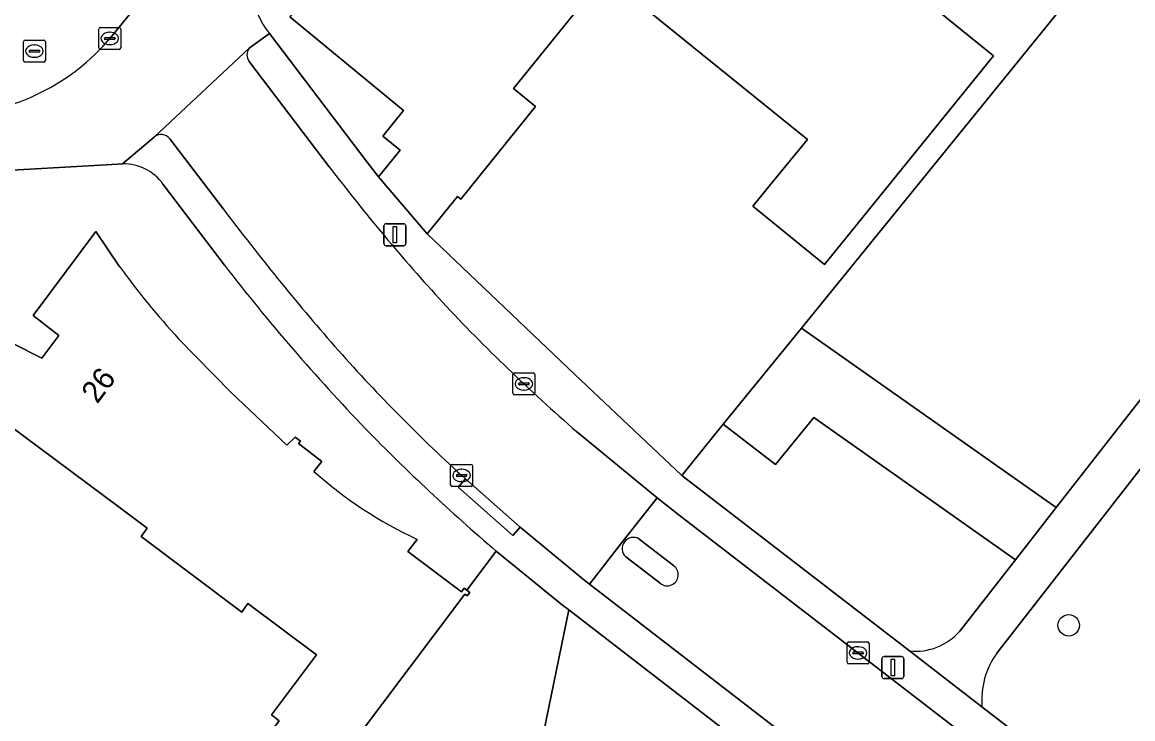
# Model space of a CAD drawing. Extents: x 159499 to 160349, y 382524 to 383273.
# Drawn here: x 159995.6 to 160046.1, y 382929.5 to 382961.2 of the extents above; entities that cross this region are included whole.
import ezdxf

# ---------------------------------------------------------------- set-up
doc = ezdxf.new("R2010")
doc.units = 0
for name, color, linetype in [('IMGEO_Boom', 7, 'Continuous'), ('IMGEO_Erf', 7, 'Continuous'), ('IMGEO_Fietspad_open', 7, 'Continuous'), ('IMGEO_Groenvoorziening', 7, 'Continuous'), ('IMGEO_Kolk', 7, 'Continuous'), ('IMGEO_Lichtmast', 7, 'Continuous'), ('IMGEO_Muur', 7, 'Continuous'), ('IMGEO_Pand', 7, 'Continuous'), ('IMGEO_Pand_nummerreeks', 7, 'Continuous'), ('IMGEO_Rijbaan_lokaal_open', 7, 'Continuous'), ('IMGEO_Rioolput', 7, 'Continuous'), ('IMGEO_Verkeerseiland_open', 7, 'Continuous'), ('IMGEO_Voetpad_halfverhard', 7, 'Continuous'), ('IMGEO_Voetpad_open', 7, 'Continuous')]:
    doc.layers.add(name, color=color, linetype=linetype)

msp = doc.modelspace()

# ---------------------------------------------------------------- linework, layer by layer
at = {"layer": 'IMGEO_Boom'}
msp.add_circle((160043.163, 382933.794), 0.489, dxfattribs=at)
at = {"layer": 'IMGEO_Erf'}
for points in [[(160035.463, 382963.138), (160039.738, 382959.678), (160032.064, 382950.194), (160028.799, 382952.836), (160029.96, 382954.246), (160031.282, 382955.879), (160022.074, 382963.331), (160017.918, 382958.195), (160018.929, 382957.378), (160015.521, 382953.167), (160015.375, 382953.286), (160014.004, 382951.592), (160020.709, 382945.19), (160025.568, 382940.607), (160027.46, 382942.936), (160031.009, 382947.305), (160052.413, 382973.653)], [(160006.829, 382960.689), (160011.264, 382954.849), (160011.78, 382954.169), (160012.771, 382955.393), (160011.986, 382956.029), (160012.916, 382957.191), (160007.749, 382961.454)], [(160000.149, 382954.763), (159999.933, 382954.745), (159991.369, 382954.262), (159973.432, 382953.353)], [(160004.784, 382950.166), (160002.003, 382953.831)], [(159975.215, 382950.328), (159980.908, 382950.668), (159981.031, 382949.203), (159983.01, 382949.322), (159986.119, 382949.51), (159986.572, 382941.868), (159989.763, 382942.076), (159989.318, 382949.49), (159995.132, 382946.61), (159996.488, 382945.938), (159997.261, 382946.967), (159996.091, 382947.877), (159998.929, 382951.684), (160000, 382950.12)], [(160002.7, 382946.812), (160005.083, 382944.371), (160007.614, 382941.975), (160007.996, 382942.341), (160008.233, 382942.163), (160008.156, 382942.059), (160009.209, 382941.236), (160008.85, 382940.79)], [(159952.688, 382921.969), (160000, 382924.568), (160007.956, 382925.066), (160009.503, 382926.949), (160006.867, 382928.928), (160007.264, 382929.458), (160006.918, 382929.718), (160008.967, 382932.449), (160005.846, 382934.79), (160005.569, 382934.389), (160000.995, 382937.827), (160001.276, 382938.205), (160000, 382939.157), (159994.951, 382942.922)], [(160013.538, 382937.7), (160013.118, 382937.14), (160015.556, 382935.309), (160015.682, 382935.477), (160015.807, 382935.383), (160017.142, 382937.168)]]:
    msp.add_lwpolyline(points, dxfattribs=at)
for centre, radius, start, end in [((160009.628, 382962.985), 3.62, 154.4733, 219.3669), ((160000.212, 382952.579), 2.185, 34.9601, 91.6628), ((160029.875, 382971.748), 36.882, 215.9029, 222.54), ((160074.156, 383003.511), 87.511, 217.55944, 223.99367), ((160074.022, 383003.922), 87.701, 224.24761, 229.56638), ((160021.675, 382955.147), 19.251, 228.2247, 244.9952)]:
    msp.add_arc(centre, radius, start, end, dxfattribs=at)
at = {"layer": 'IMGEO_Fietspad_open'}
for points in [[(160005.908, 382960.021), (160001.602, 382955.996)], [(160009.545, 382954.631), (160005.905, 382959.423)], [(160002.3, 382955.907), (160004.746, 382952.7)], [(160015.569, 382940.601), (160015.738, 382940.446), (160018.22, 382938.246), (160021.106, 382935.882), (160021.378, 382935.67), (160022.909, 382937.636), (160024.456, 382939.589), (160020.788, 382942.6)], [(160025.459, 382938.803), (160024.456, 382939.589), (160022.909, 382937.636), (160021.378, 382935.67), (160063.074, 382903.483), (160066.117, 382901.155), (160068.062, 382899.707), (160072.665, 382896.136)], [(160076.227, 382899.664), (160069.998, 382904.476), (160025.459, 382938.803)], [(160023.624, 382937.724), (160025.194, 382936.508)], [(160024.589, 382935.703), (160023.026, 382936.902)]]:
    msp.add_lwpolyline(points, dxfattribs=at)
for centre, radius, start, end in [((160006.291, 382959.72), 0.487, 141.8673, 217.5579), ((160001.906, 382955.602), 0.498, 37.7654, 127.7017), ((160081.386, 383009.489), 90.391, 217.36539, 222.45416), ((160092.923, 383019.042), 110.347, 216.95678, 221.11214), ((160075.343, 383005.287), 83.102, 223.12889, 228.96758), ((160068.005, 382997.931), 77.694, 221.46522, 227.5527), ((160023.377, 382937.276), 0.512, 61.093, 142.5695), ((160023.361, 382937.274), 0.501, 141.3505, 227.9967), ((160024.908, 382936.093), 0.504, 230.689, 55.4574)]:
    msp.add_arc(centre, radius, start, end, dxfattribs=at)
at = {"layer": 'IMGEO_Groenvoorziening'}
for points in [[(160064.767, 383037.736), (160064.154, 383036.884), (160086.515, 383015.238), (160074.019, 383000), (160052.413, 382973.653), (160031.009, 382947.305), (160042.591, 382939.142), (160050.543, 382949.325), (160056.483, 382957.417)], [(160039.216, 382930.091), (160066.447, 382909.109), (160081.958, 382927.957), (160078.777, 382930.867), (160081.343, 382933.929), (160066.591, 382946.291), (160078.07, 382965.324), (160067.823, 382973.903)], [(160064.191, 382966.975), (160061.224, 382961.584), (160058.065, 382956.302), (160055.15, 382952.189), (160052.089, 382948.183), (160039.892, 382932.533)], [(160038.205, 382933.526), (160040.742, 382936.775), (160031.571, 382943.239), (160029.837, 382941.105), (160027.46, 382942.936), (160025.568, 382940.607), (160035.923, 382932.628)], [(160017.276, 382919.096), (160020.444, 382934.49), (160020.156, 382934.712), (160017.142, 382937.168), (160015.807, 382935.383), (160015.93, 382935.29), (160015.81, 382935.13), (160015.706, 382935.209), (160009.503, 382926.949), (160007.956, 382925.066), (160000, 382924.568), (159952.688, 382921.969), (159935.493, 382907.023), (159936.535, 382905.918), (159939.597, 382902.666), (159962.238, 382916.541), (159978.374, 382915.464)], [(160030.14, 382927.014), (160020.444, 382934.49), (160017.276, 382919.096)]]:
    msp.add_lwpolyline(points, dxfattribs=at)
msp.add_lwpolyline([(160031.009, 382947.305), (160027.46, 382942.936), (160029.837, 382941.105), (160031.571, 382943.239), (160040.742, 382936.775), (160042.591, 382939.142)], close=True, dxfattribs=at)
for centre, radius, start, end in [((160036.194, 382935.288), 2.674, 264.1891, 318.7716), ((160042.931, 382930.377), 3.726, 144.6503, 184.4032)]:
    msp.add_arc(centre, radius, start, end, dxfattribs=at)
at = {"layer": 'IMGEO_Kolk'}
for p, q in [((159999.141, 382960.965), (159999.993, 382960.965)), ((159999.066, 382960.039), (159999.066, 382960.891)), ((159999.325, 382960.459), (159999.325, 382960.471)), ((159999.763, 382960.422), (159999.365, 382960.422)), ((159999.368, 382960.508), (159999.766, 382960.508)), ((159999.554, 382960.745), (159999.579, 382960.745)), ((159999.809, 382960.471), (159999.809, 382960.459)), ((160000.067, 382960.891), (160000.067, 382960.039)), ((159999.993, 382959.965), (159999.141, 382959.965)), ((159999.577, 382960.185), (159999.552, 382960.185)), ((160017.896, 382944.34), (160017.896, 382945.192)), ((160017.971, 382945.266), (160018.823, 382945.266)), ((160018.155, 382944.76), (160018.155, 382944.772)), ((160018.198, 382944.809), (160018.596, 382944.809)), ((160018.384, 382945.046), (160018.409, 382945.046)), ((160018.639, 382944.772), (160018.639, 382944.76)), ((160018.897, 382945.192), (160018.897, 382944.34)), ((160018.823, 382944.266), (160017.971, 382944.266)), ((160018.593, 382944.723), (160018.195, 382944.723)), ((160018.407, 382944.486), (160018.382, 382944.486)), ((160015.065, 382940.177), (160015.065, 382941.029)), ((160015.14, 382941.103), (160015.992, 382941.103)), ((160015.553, 382940.883), (160015.578, 382940.883)), ((160016.066, 382941.029), (160016.066, 382940.177)), ((160015.324, 382940.597), (160015.324, 382940.609)), ((160015.762, 382940.56), (160015.364, 382940.56)), ((160015.367, 382940.646), (160015.765, 382940.646)), ((160015.576, 382940.323), (160015.551, 382940.323)), ((160015.808, 382940.609), (160015.808, 382940.597)), ((160015.992, 382940.103), (160015.14, 382940.103)), ((160033.086, 382932.111), (160033.086, 382932.963)), ((160033.161, 382933.037), (160034.013, 382933.037)), ((160033.574, 382932.817), (160033.599, 382932.817)), ((160034.087, 382932.963), (160034.087, 382932.111)), ((160033.345, 382932.531), (160033.345, 382932.543)), ((160033.783, 382932.494), (160033.385, 382932.494)), ((160033.388, 382932.58), (160033.786, 382932.58)), ((160033.597, 382932.257), (160033.572, 382932.257)), ((160033.829, 382932.543), (160033.829, 382932.531)), ((160034.013, 382932.037), (160033.161, 382932.037))]:
    msp.add_line(p, q, dxfattribs=at)
for points in [[(159999.141, 382960.965), (159999.993, 382960.965)], [(159999.066, 382960.039), (159999.066, 382960.891)], [(160000.067, 382960.891), (160000.067, 382960.039)], [(159999.993, 382959.965), (159999.141, 382959.965)], [(160017.896, 382944.34), (160017.896, 382945.192)], [(160017.971, 382945.266), (160018.823, 382945.266)], [(160018.897, 382945.192), (160018.897, 382944.34)], [(160018.823, 382944.266), (160017.971, 382944.266)], [(160015.065, 382940.177), (160015.065, 382941.029)], [(160015.14, 382941.103), (160015.992, 382941.103)], [(160016.066, 382941.029), (160016.066, 382940.177)], [(160015.992, 382940.103), (160015.14, 382940.103)], [(160033.086, 382932.111), (160033.086, 382932.963)], [(160033.161, 382933.037), (160034.013, 382933.037)], [(160034.087, 382932.963), (160034.087, 382932.111)], [(160034.013, 382932.037), (160033.161, 382932.037)]]:
    msp.add_lwpolyline(points, dxfattribs=at)
for centre, radius, start, end in [((159999.143, 382960.889), 0.0765, 91.552, 178.448), ((159999.143, 382960.889), 0.0765, 91.552, 178.448), ((159999.991, 382960.889), 0.0765, 1.552, 88.448), ((159999.991, 382960.889), 0.0765, 1.552, 88.448), ((159999.365, 382960.468), 0.0403, 85.8775, 175.7526), ((159999.362, 382960.458), 0.0366, 178.938, 274.7102), ((159999.766, 382960.465), 0.043, 264.8664, 352.4533), ((159999.77, 382960.47), 0.0386, 1.7309, 96.639), ((159999.143, 382960.041), 0.0765, 181.552, 268.448), ((159999.143, 382960.041), 0.0765, 181.552, 268.448), ((159999.991, 382960.041), 0.0765, 271.552, 358.448), ((159999.991, 382960.041), 0.0765, 271.552, 358.448), ((160017.973, 382945.19), 0.0765, 91.552, 178.448), ((160017.973, 382945.19), 0.0765, 91.552, 178.448), ((160018.195, 382944.769), 0.0403, 85.8775, 175.7526), ((160018.6, 382944.771), 0.0386, 1.7309, 96.639), ((160018.821, 382945.19), 0.0765, 1.552, 88.448), ((160018.821, 382945.19), 0.0765, 1.552, 88.448), ((160017.973, 382944.342), 0.0765, 181.552, 268.448), ((160017.973, 382944.342), 0.0765, 181.552, 268.448), ((160018.192, 382944.759), 0.0366, 178.938, 274.7102), ((160018.596, 382944.766), 0.043, 264.8664, 352.4533), ((160018.821, 382944.342), 0.0765, 271.552, 358.448), ((160018.821, 382944.342), 0.0765, 271.552, 358.448), ((160015.142, 382941.027), 0.0765, 91.552, 178.448), ((160015.142, 382941.027), 0.0765, 91.552, 178.448), ((160015.99, 382941.027), 0.0765, 1.552, 88.448), ((160015.99, 382941.027), 0.0765, 1.552, 88.448), ((160015.364, 382940.606), 0.0403, 85.8775, 175.7526), ((160015.361, 382940.596), 0.0366, 178.938, 274.7102), ((160015.765, 382940.603), 0.043, 264.8664, 352.4533), ((160015.769, 382940.608), 0.0386, 1.7309, 96.639), ((160015.142, 382940.179), 0.0765, 181.552, 268.448), ((160015.142, 382940.179), 0.0765, 181.552, 268.448), ((160015.99, 382940.179), 0.0765, 271.552, 358.448), ((160015.99, 382940.179), 0.0765, 271.552, 358.448), ((160033.163, 382932.961), 0.0765, 91.552, 178.448), ((160033.163, 382932.961), 0.0765, 91.552, 178.448), ((160034.011, 382932.961), 0.0765, 1.552, 88.448), ((160034.011, 382932.961), 0.0765, 1.552, 88.448), ((160033.385, 382932.54), 0.0403, 85.8775, 175.7526), ((160033.382, 382932.53), 0.0366, 178.938, 274.7102), ((160033.786, 382932.537), 0.043, 264.8664, 352.4533), ((160033.79, 382932.542), 0.0386, 1.7309, 96.639), ((160033.163, 382932.113), 0.0765, 181.552, 268.448), ((160033.163, 382932.113), 0.0765, 181.552, 268.448), ((160034.011, 382932.113), 0.0765, 271.552, 358.448), ((160034.011, 382932.113), 0.0765, 271.552, 358.448)]:
    msp.add_arc(centre, radius, start, end, dxfattribs=at)
for centre, major_axis, ratio, start_param, end_param in [((159999.553, 382960.465), (-0.387, 0.002), 0.722429, 4.712389, 7.853982), ((159999.578, 382960.465), (-0.39, 0.002), 0.717154, 1.570796, 4.712389), ((160018.383, 382944.766), (-0.387, 0.002), 0.722429, 4.712389, 7.853982), ((160018.408, 382944.766), (-0.39, 0.002), 0.717154, 1.570796, 4.712389), ((160015.552, 382940.603), (-0.387, 0.002), 0.722429, 4.712389, 7.853982), ((160015.577, 382940.603), (-0.39, 0.002), 0.717154, 1.570796, 4.712389), ((160033.573, 382932.537), (-0.387, 0.002), 0.722429, 4.712389, 7.853982), ((160033.598, 382932.537), (-0.39, 0.002), 0.717154, 1.570796, 4.712389)]:
    msp.add_ellipse(centre, major_axis=major_axis, ratio=ratio, start_param=start_param, end_param=end_param, dxfattribs=at)
at = {"layer": 'IMGEO_Lichtmast'}
for p, q in [((160012.033, 382951.144), (160012.033, 382951.944)), ((160012.033, 382951.944), (160012.033, 382951.144)), ((160012.133, 382952.044), (160012.923, 382952.044)), ((160012.923, 382952.044), (160012.133, 382952.044)), ((160013.023, 382951.944), (160013.023, 382951.144)), ((160013.023, 382951.144), (160013.023, 382951.944)), ((160012.923, 382951.044), (160012.133, 382951.044)), ((160012.133, 382951.044), (160012.923, 382951.044)), ((160034.672, 382931.473), (160034.672, 382932.273)), ((160034.672, 382932.273), (160034.672, 382931.473)), ((160034.772, 382932.373), (160035.562, 382932.373)), ((160035.562, 382932.373), (160034.772, 382932.373)), ((160035.662, 382932.273), (160035.662, 382931.473)), ((160035.662, 382931.473), (160035.662, 382932.273)), ((160035.562, 382931.373), (160034.772, 382931.373)), ((160034.772, 382931.373), (160035.562, 382931.373))]:
    msp.add_line(p, q, dxfattribs=at)
for points in [[(160012.453, 382951.919), (160012.603, 382951.919), (160012.603, 382951.169), (160012.453, 382951.169), (160012.453, 382951.919)], [(160035.092, 382932.248), (160035.242, 382932.248), (160035.242, 382931.498), (160035.092, 382931.498), (160035.092, 382932.248)]]:
    msp.add_lwpolyline(points, dxfattribs=at)
for centre, start, end in [((160012.133, 382951.944), 90, 180), ((160012.133, 382951.944), 90, 180), ((160012.923, 382951.944), 0, 90), ((160012.923, 382951.944), 360, 90), ((160012.133, 382951.144), 180, 270), ((160012.133, 382951.144), 180, 270), ((160012.923, 382951.144), 270, 0), ((160012.923, 382951.144), 270, 0), ((160034.772, 382932.273), 90, 180), ((160034.772, 382932.273), 90, 180), ((160035.562, 382932.273), 0, 90), ((160035.562, 382932.273), 360, 90), ((160034.772, 382931.473), 180, 270), ((160034.772, 382931.473), 180, 270), ((160035.562, 382931.473), 270, 0), ((160035.562, 382931.473), 270, 0)]:
    msp.add_arc(centre, 0.1, start, end, dxfattribs=at)
at = {"layer": 'IMGEO_Muur'}
msp.add_lwpolyline([(160014.004, 382951.592), (160020.709, 382945.19)], dxfattribs=at)
at = {"layer": 'IMGEO_Pand'}
msp.add_lwpolyline([(160014.004, 382951.592), (160015.375, 382953.286), (160015.521, 382953.167), (160018.929, 382957.378), (160017.918, 382958.195), (160022.074, 382963.331), (160031.282, 382955.879), (160029.96, 382954.246), (160028.799, 382952.836), (160032.064, 382950.194), (160039.738, 382959.678), (160035.463, 382963.138), (160034.771, 382962.282), (160024.597, 382970.514), (160020.71, 382973.659), (160017.292, 382969.479), (160016.393, 382970.234), (160013.346, 382966.541), (160012.437, 382967.265), (160007.749, 382961.454), (160012.916, 382957.191), (160011.986, 382956.029), (160012.771, 382955.393), (160011.78, 382954.169)], close=True, dxfattribs=at)
for points in [[(160000, 382950.12), (159998.929, 382951.684), (159996.091, 382947.877), (159997.261, 382946.967), (159996.488, 382945.938), (159995.132, 382946.61)], [(160008.85, 382940.79), (160009.209, 382941.236), (160008.156, 382942.059), (160008.233, 382942.163), (160007.996, 382942.341), (160007.614, 382941.975), (160005.083, 382944.371), (160002.7, 382946.812)], [(159994.951, 382942.922), (160000, 382939.157), (160001.276, 382938.205), (160000.995, 382937.827), (160005.569, 382934.389), (160005.846, 382934.79), (160008.967, 382932.449), (160006.918, 382929.718), (160007.264, 382929.458), (160006.867, 382928.928), (160009.503, 382926.949), (160015.706, 382935.209), (160015.81, 382935.13), (160015.93, 382935.29), (160015.807, 382935.383), (160015.682, 382935.477), (160015.556, 382935.309), (160013.118, 382937.14), (160013.538, 382937.7)]]:
    msp.add_lwpolyline(points, dxfattribs=at)
for centre, radius, start, end in [((160029.875, 382971.748), 36.882, 215.9029, 222.54), ((160021.675, 382955.147), 19.251, 228.2247, 244.9952)]:
    msp.add_arc(centre, radius, start, end, dxfattribs=at)
at = {"layer": 'IMGEO_Rijbaan_lokaal_open'}
for points in [[(159999.59, 382960.475), (160000, 382960.98), (160004.421, 382966.424), (160007.59, 382970.326), (160016.821, 382981.656), (160020, 382985.559), (160027.604, 382994.891), (160030.786, 382998.795)], [(160006.361, 382964.545), (160005.808, 382965.295), (160004.421, 382966.424), (160000, 382960.98), (159999.59, 382960.475)], [(159973.432, 382953.353), (159991.369, 382954.262), (159999.933, 382954.745), (160000.149, 382954.763), (160001.602, 382955.996), (160005.908, 382960.021), (160006.829, 382960.689)]]:
    msp.add_lwpolyline(points, dxfattribs=at)
for centre, radius, start, end in [((160009.628, 382962.985), 3.62, 154.4733, 219.3669), ((159991.946, 382966.989), 10.043, 273.4358, 319.5641), ((159991.946, 382966.989), 10.043, 273.4358, 319.5641)]:
    msp.add_arc(centre, radius, start, end, dxfattribs=at)
at = {"layer": 'IMGEO_Rioolput'}
for p, q in [((159995.643, 382959.463), (159995.643, 382960.315)), ((159995.718, 382960.389), (159996.57, 382960.389)), ((159995.945, 382959.932), (159996.343, 382959.932)), ((159996.131, 382960.169), (159996.156, 382960.169)), ((159996.644, 382960.315), (159996.644, 382959.463)), ((159995.902, 382959.883), (159995.902, 382959.895)), ((159996.34, 382959.846), (159995.942, 382959.846)), ((159996.154, 382959.609), (159996.129, 382959.609)), ((159996.386, 382959.895), (159996.386, 382959.883)), ((159996.57, 382959.389), (159995.718, 382959.389))]:
    msp.add_line(p, q, dxfattribs=at)
for points in [[(159995.643, 382959.463), (159995.643, 382960.315)], [(159995.718, 382960.389), (159996.57, 382960.389)], [(159996.644, 382960.315), (159996.644, 382959.463)], [(159996.57, 382959.389), (159995.718, 382959.389)]]:
    msp.add_lwpolyline(points, dxfattribs=at)
for centre, radius, start, end in [((159995.72, 382960.313), 0.0765, 91.552, 178.448), ((159995.72, 382960.313), 0.0765, 91.552, 178.448), ((159995.942, 382959.892), 0.0403, 85.8775, 175.7526), ((159996.347, 382959.894), 0.0386, 1.7309, 96.639), ((159996.568, 382960.313), 0.0765, 1.552, 88.448), ((159996.568, 382960.313), 0.0765, 1.552, 88.448), ((159995.72, 382959.465), 0.0765, 181.552, 268.448), ((159995.72, 382959.465), 0.0765, 181.552, 268.448), ((159995.939, 382959.882), 0.0366, 178.938, 274.7102), ((159996.343, 382959.889), 0.043, 264.8664, 352.4533), ((159996.568, 382959.465), 0.0765, 271.552, 358.448), ((159996.568, 382959.465), 0.0765, 271.552, 358.448)]:
    msp.add_arc(centre, radius, start, end, dxfattribs=at)
for centre, major_axis, ratio, start_param, end_param in [((159996.13, 382959.889), (-0.387, 0.002), 0.722429, 4.712389, 7.853982), ((159996.155, 382959.889), (-0.39, 0.002), 0.717154, 1.570796, 4.712389)]:
    msp.add_ellipse(centre, major_axis=major_axis, ratio=ratio, start_param=start_param, end_param=end_param, dxfattribs=at)
at = {"layer": 'IMGEO_Verkeerseiland_open'}
for points in [[(160025.194, 382936.508), (160023.624, 382937.724)], [(160023.026, 382936.902), (160024.589, 382935.703)]]:
    msp.add_lwpolyline(points, dxfattribs=at)
for centre, radius, start, end in [((160023.377, 382937.276), 0.512, 61.093, 142.5695), ((160023.361, 382937.274), 0.501, 141.3505, 227.9967), ((160024.908, 382936.093), 0.504, 230.689, 55.4574)]:
    msp.add_arc(centre, radius, start, end, dxfattribs=at)
at = {"layer": 'IMGEO_Voetpad_halfverhard'}
for points in [[(160039.892, 382932.533), (160052.089, 382948.183), (160055.15, 382952.189), (160058.065, 382956.302), (160061.224, 382961.584), (160064.191, 382966.975)], [(160056.483, 382957.417), (160050.543, 382949.325), (160042.591, 382939.142), (160040.742, 382936.775), (160038.205, 382933.526)], [(160035.923, 382932.628), (160039.216, 382930.091)]]:
    msp.add_lwpolyline(points, dxfattribs=at)
for centre, radius, start, end in [((160036.194, 382935.288), 2.674, 264.1891, 318.7716), ((160042.931, 382930.377), 3.726, 144.6503, 184.4032)]:
    msp.add_arc(centre, radius, start, end, dxfattribs=at)
at = {"layer": 'IMGEO_Voetpad_open'}
for points in [[(160039.216, 382930.091), (160035.923, 382932.628), (160025.568, 382940.607), (160020.709, 382945.19), (160014.004, 382951.592), (160011.78, 382954.169), (160011.264, 382954.849), (160006.829, 382960.689), (160005.908, 382960.021)], [(160005.905, 382959.423), (160009.545, 382954.631)], [(160001.602, 382955.996), (160000.149, 382954.763)], [(160004.746, 382952.7), (160002.3, 382955.907)], [(160002.003, 382953.831), (160004.784, 382950.166)], [(160020.788, 382942.6), (160024.456, 382939.589), (160025.459, 382938.803), (160069.998, 382904.476), (160076.227, 382899.664)], [(160021.378, 382935.67), (160021.106, 382935.882), (160018.22, 382938.246), (160017.889, 382937.872), (160015.407, 382940.072), (160015.738, 382940.446), (160015.569, 382940.601)], [(160017.142, 382937.168), (160020.156, 382934.712), (160020.444, 382934.49), (160030.14, 382927.014), (160034.47, 382923.674), (160034.617, 382923.561), (160052.844, 382909.5), (160060.881, 382903.305), (160062.494, 382902.039), (160066.336, 382899.068), (160073.682, 382893.351)], [(160072.665, 382896.136), (160068.062, 382899.707), (160066.117, 382901.155), (160063.074, 382903.483), (160021.378, 382935.67)], [(160079.146, 382899.286), (160068.039, 382907.853), (160066.447, 382909.109), (160039.216, 382930.091)]]:
    msp.add_lwpolyline(points, dxfattribs=at)
msp.add_lwpolyline([(160015.738, 382940.446), (160015.407, 382940.072), (160017.889, 382937.872), (160018.22, 382938.246)], close=True, dxfattribs=at)
for centre, radius, start, end in [((160006.291, 382959.72), 0.487, 141.8673, 217.5579), ((160001.906, 382955.602), 0.498, 37.7654, 127.7017), ((160000.212, 382952.579), 2.185, 34.9601, 91.6628), ((160081.386, 383009.489), 90.391, 217.36539, 222.45416), ((160092.923, 383019.042), 110.347, 216.95678, 221.11214), ((160074.156, 383003.511), 87.511, 217.55944, 223.99367), ((160075.343, 383005.287), 83.102, 223.12889, 228.96758), ((160068.005, 382997.931), 77.694, 221.46522, 227.5527), ((160074.022, 383003.922), 87.701, 224.24761, 229.56638)]:
    msp.add_arc(centre, radius, start, end, dxfattribs=at)

# ---------------------------------------------------------------- texts
at = {"layer": 'IMGEO_Pand_nummerreeks'}
msp.add_text('26', height=1, rotation=53.0856, dxfattribs=at).set_placement((159999.001, 382943.822))

doc.saveas('drawing.dxf')
